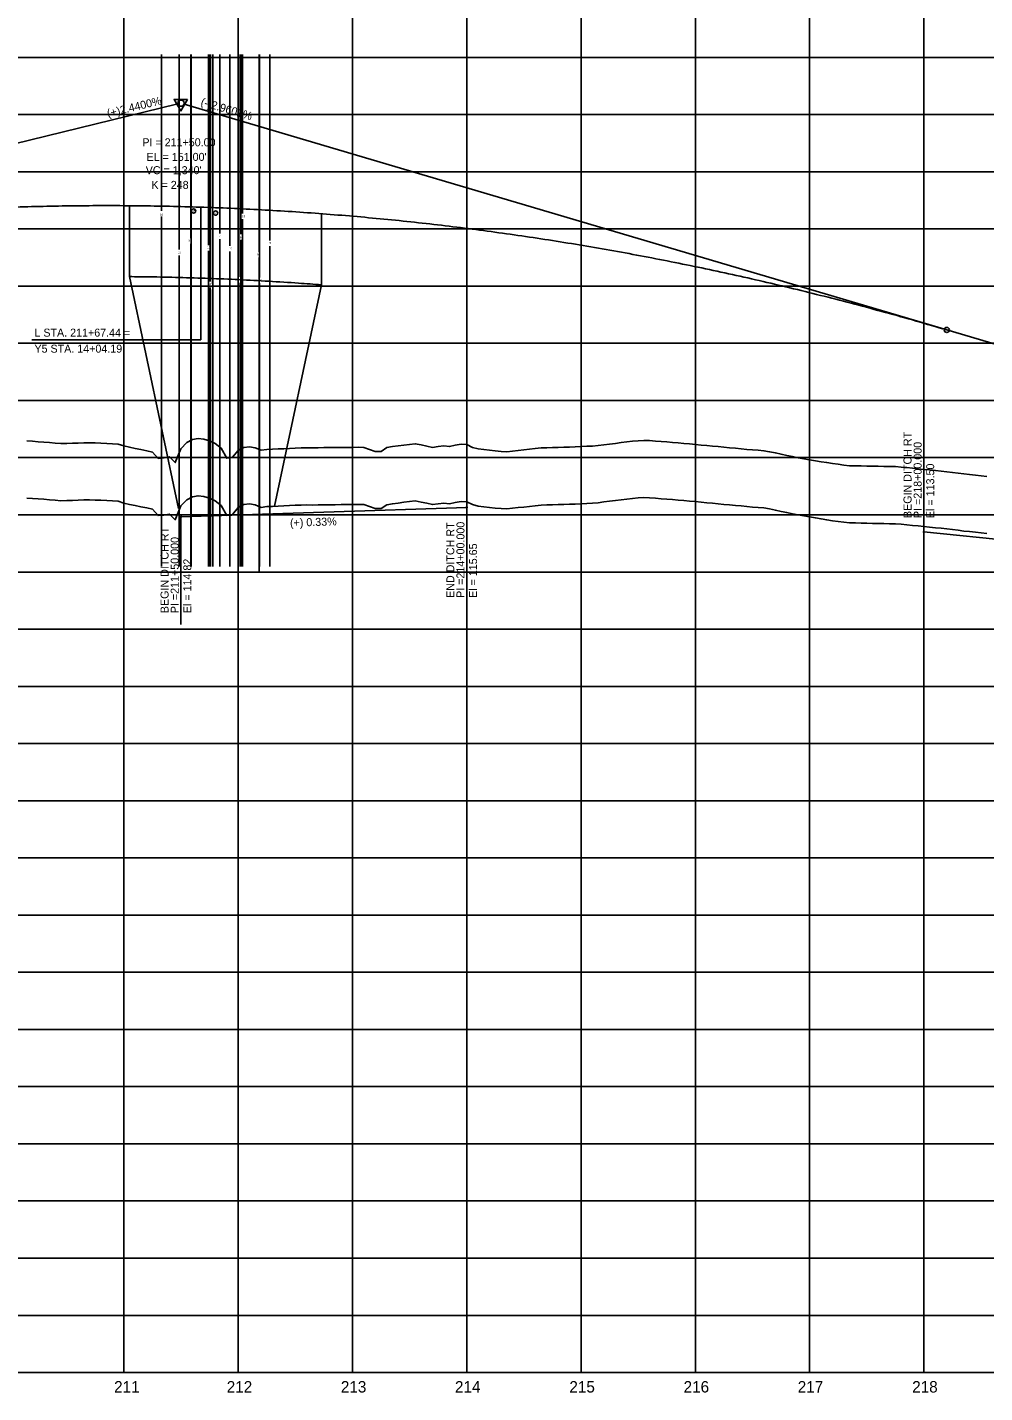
# Model space of a CAD drawing. Extents: x 2345490 to 2445302, y 465165 to 573888.
# Drawn here: x 2401337 to 2402175, y 564259 to 565453 of the extents above; entities that cross this region are included whole.
import ezdxf

# ---------------------------------------------------------------- set-up
doc = ezdxf.new("R2010")
doc.units = 0
for name, color, linetype in [('Old_Level_1', 7, 'Continuous'), ('Old_Level_2', 7, 'Continuous'), ('Old_Level_3', 7, 'Continuous'), ('Old_Level_57', 7, 'Continuous'), ('Old_Level_6', 7, 'Continuous'), ('Old_Level_62', 7, 'Continuous'), ('Old_Level_63', 7, 'Continuous')]:
    doc.layers.add(name, color=color, linetype=linetype)

msp = doc.modelspace()

# ---------------------------------------------------------------- linework, layer by layer
at = {"layer": 'Old_Level_1'}
for points in [[(2401336.5425, 565041.219), (2401341.5425, 565040.8905), (2401346.5425, 565040.512), (2401351.5425, 565040.09675), (2401356.5425, 565039.682), (2401361.5425, 565039.268), (2401366.5425, 565038.8545), (2401371.5425, 565038.982)], [(2401371.5425, 565038.982), (2401376.5425, 565039.15775), (2401381.5425, 565039.33375), (2401386.5425, 565039.5105), (2401391.5425, 565039.56925), (2401396.5425, 565039.418), (2401401.5425, 565039.24675), (2401406.5425, 565038.94875), (2401411.5425, 565038.652), (2401416.5425, 565038.3565), (2401421.5425, 565036.73225), (2401426.5425, 565035.699), (2401431.5425, 565034.66925), (2401436.5425, 565033.6435), (2401441.5425, 565032.6215), (2401446.5425, 565031.472), (2401451.5425, 565025.84975), (2401456.5425, 565026.37225), (2401461.5425, 565027.25675), (2401466.5425, 565022.21175), (2401471.5425, 565034.33175), (2401476.5425, 565039.72925), (2401481.5425, 565042.39775), (2401486.5425, 565043.2485), (2401491.5425, 565042.71025), (2401496.5425, 565041.198), (2401501.5425, 565038.84875), (2401506.5425, 565034.692), (2401511.5425, 565025.9635), (2401516.5425, 565026.869), (2401521.5425, 565032.8215), (2401526.5425, 565035.4635), (2401531.5425, 565036.07075), (2401536.5425, 565035.26475), (2401541.5425, 565032.9655), (2401546.5425, 565033.726), (2401551.5425, 565033.946), (2401556.5425, 565034.16775), (2401561.5425, 565034.39075), (2401566.5425, 565034.6155), (2401571.5425, 565034.842), (2401576.5425, 565035.06975), (2401581.5425, 565035.18775), (2401586.5425, 565035.1115), (2401591.5425, 565035.193), (2401596.5425, 565035.27525), (2401601.5425, 565035.35775), (2401606.5425, 565035.42275), (2401611.5425, 565035.4595), (2401616.5425, 565035.49725), (2401621.5425, 565035.53675), (2401626.5425, 565035.5775), (2401631.5425, 565035.5155), (2401636.5425, 565033.74), (2401641.5425, 565031.964), (2401646.5425, 565032.00875), (2401651.5425, 565035.38175), (2401656.5425, 565036.27475), (2401661.5425, 565036.8745), (2401666.5425, 565037.47475), (2401671.5425, 565038.07525), (2401676.5425, 565038.676), (2401681.5425, 565037.7145), (2401686.5425, 565036.6275), (2401691.5425, 565035.5405), (2401696.5425, 565036.1865), (2401701.5425, 565036.87), (2401706.5425, 565036.2335), (2401711.5425, 565037.34725), (2401716.5425, 565038.19), (2401721.5425, 565038.01175), (2401726.5425, 565035.504), (2401731.5425, 565034.129), (2401736.5425, 565033.57725), (2401741.5425, 565033.02725), (2401746.5425, 565032.47925), (2401751.5425, 565031.93325), (2401756.5425, 565031.67525), (2401761.5425, 565032.238), (2401766.5425, 565032.80225), (2401771.5425, 565033.36825), (2401776.5425, 565033.93575), (2401781.5425, 565034.50475), (2401786.5425, 565035.07525), (2401791.5425, 565035.27025), (2401796.5425, 565035.39175), (2401801.5425, 565035.51425), (2401806.5425, 565035.638), (2401811.5425, 565035.7625), (2401816.5425, 565035.9865), (2401821.5425, 565036.213), (2401826.5425, 565036.44075), (2401831.5425, 565036.66925), (2401836.5425, 565037.1695), (2401841.5425, 565037.7945), (2401846.5425, 565038.42075), (2401851.5425, 565039.0485), (2401856.5425, 565039.6775), (2401861.5425, 565040.30825), (2401866.5425, 565040.94025), (2401871.5425, 565041.3565)], [(2401871.5425, 565041.3565), (2401876.5425, 565041.65925), (2401881.5425, 565041.50575), (2401886.5425, 565041.07875), (2401891.5425, 565040.65225), (2401896.5425, 565040.22675), (2401901.5425, 565039.802), (2401906.5425, 565039.37825), (2401911.5425, 565038.95525), (2401916.5425, 565038.534), (2401921.5425, 565038.17625), (2401926.5425, 565037.58), (2401931.5425, 565037.10425), (2401936.5425, 565036.62875), (2401941.5425, 565036.154), (2401946.5425, 565035.6795), (2401951.5425, 565035.20575), (2401956.5425, 565034.73225), (2401961.5425, 565034.25925), (2401966.5425, 565033.78675), (2401971.5425, 565033.378), (2401976.5425, 565032.9915), (2401981.5425, 565032.6055), (2401986.5425, 565031.66725), (2401991.5425, 565030.61), (2401996.5425, 565029.5535), (2402001.5425, 565028.49775), (2402006.5425, 565027.44325), (2402011.5425, 565026.45875), (2402016.5425, 565025.5975), (2402021.5425, 565024.7365), (2402026.5425, 565023.876), (2402031.5425, 565023.01575), (2402036.5425, 565022.15575), (2402041.5425, 565021.36075), (2402046.5425, 565020.7135), (2402051.5425, 565020.06675), (2402056.5425, 565019.50775), (2402061.5425, 565019.4025), (2402066.5425, 565019.29775), (2402071.5425, 565019.19375), (2402076.5425, 565019.0905), (2402081.5425, 565018.988), (2402086.5425, 565018.886), (2402091.5425, 565018.78475), (2402096.5425, 565018.68425), (2402101.5425, 565018.322), (2402106.5425, 565017.81675), (2402111.5425, 565017.30675), (2402116.5425, 565016.79775), (2402121.5425, 565016.2895), (2402126.5425, 565015.78175), (2402131.5425, 565015.27475), (2402136.5425, 565014.7685), (2402141.5425, 565014.263), (2402146.5425, 565013.64675), (2402151.5425, 565013.01075), (2402156.5425, 565012.37925), (2402161.5425, 565011.824), (2402166.5425, 565011.2695), (2402171.5425, 565010.7155), (2402176.5425, 565010.162)]]:
    msp.add_lwpolyline(points, dxfattribs=at)
at = {"layer": 'Old_Level_2'}
for p, q in [((2400801.5425, 565223.054), (2401468.871, 565385.882)), ((2402141.5425, 565188.20425), (2401474.1795, 565385.75325)), ((2402141.5425, 565188.20425), (2402451.5425, 565096.43975))]:
    msp.add_line(p, q, dxfattribs=at)
msp.add_lwpolyline([(2401477.299, 565389.86625), (2401465.5565, 565389.85175), (2401471.44, 565379.7335)], close=True, dxfattribs=at)
for centre, radius in [((2401471.5425, 565386.534), 2.75), ((2402141.5425, 565188.20425), 2.25)]:
    msp.add_circle(centre, radius, dxfattribs=at)
msp.add_spline([(2400801.5425, 565223.054), (2400828.3425, 565229.44825), (2400855.1425, 565235.5535), (2400881.9425, 565241.369), (2400908.7425, 565246.895), (2400935.5425, 565252.13175), (2400962.3425, 565257.079), (2400989.1425, 565261.73675), (2401015.9425, 565266.10525), (2401042.7425, 565270.184), (2401069.5425, 565273.9735), (2401096.3425, 565277.4735), (2401123.1425, 565280.684), (2401149.9425, 565283.60525), (2401176.7425, 565286.23675), (2401203.5425, 565288.579), (2401230.3425, 565290.63175), (2401257.1425, 565292.395), (2401283.9425, 565293.869), (2401310.7425, 565295.05325), (2401337.5425, 565295.94825), (2401364.3425, 565296.55375), (2401391.1425, 565296.87), (2401417.9425, 565296.8965), (2401444.7425, 565296.63375), (2401471.5425, 565296.0815), (2401498.3425, 565295.23975), (2401525.1425, 565294.1085), (2401551.9425, 565292.688), (2401578.7425, 565290.978), (2401605.5425, 565288.9785), (2401632.3425, 565286.6895), (2401659.1425, 565284.111), (2401685.9425, 565281.24325), (2401712.7425, 565278.08575), (2401739.5425, 565274.639), (2401766.3425, 565270.903), (2401793.1425, 565266.87725), (2401819.9425, 565262.56225), (2401846.7425, 565257.95775), (2401873.5425, 565253.06375), (2401900.3425, 565247.88025), (2401927.1425, 565242.40725), (2401953.9425, 565236.645), (2401980.7425, 565230.59325), (2402007.5425, 565224.252), (2402034.3425, 565217.62125), (2402061.1425, 565210.70125), (2402087.9425, 565203.49175), (2402114.7425, 565195.99275), (2402141.5425, 565188.20425)], degree=3, dxfattribs=at)
at = {"layer": 'Old_Level_3'}
for p, q in [((2401488.9825, 565179.50175), (2401488.9825, 565295.56525)), ((2401341.176, 565179.50175), (2401488.9825, 565179.50175)), ((2402121.5425, 565098.35758), (2402121.5425, 565011.534)), ((2401471.5425, 565024.734), (2401721.5425, 565033.034)), ((2401721.5425, 565033.034), (2401721.5425, 564946.21042)), ((2401471.5425, 565024.734), (2401471.5425, 564930.52205)), ((2402121.5425, 565011.534), (2402371.5425, 564986.534))]:
    msp.add_line(p, q, dxfattribs=at)
for centre in [(2401721.5425, 565033.034), (2401471.5425, 565024.734), (2402121.5425, 565011.534)]:
    msp.add_circle(centre, 0.5, dxfattribs=at)
at = {"layer": 'Old_Level_57'}
for p, q in [((2401421.54225, 564276.534), (2401421.54225, 566615.2835)), ((2401521.54225, 564276.534), (2401521.54225, 566615.2835)), ((2401621.54225, 564276.534), (2401621.54225, 566615.2835)), ((2401721.54225, 564276.534), (2401721.54225, 566615.2835)), ((2401821.54225, 564276.534), (2401821.54225, 566615.2835)), ((2401921.54225, 564276.534), (2401921.54225, 566615.2835)), ((2402021.54225, 564276.534), (2402021.54225, 566615.2835)), ((2402121.54225, 564276.534), (2402121.54225, 566615.2835)), ((2381271.5425, 565426.534), (2410861.12275, 565426.534)), ((2381271.5425, 565376.534), (2410861.12275, 565376.534)), ((2381271.5425, 565326.534), (2410861.12275, 565326.534)), ((2381271.5425, 565276.534), (2410861.12275, 565276.534)), ((2381271.5425, 565226.534), (2410861.12275, 565226.534)), ((2381271.5425, 565176.534), (2410861.12275, 565176.534)), ((2381271.5425, 565126.534), (2410861.12275, 565126.534)), ((2381271.5425, 565076.534), (2410861.12275, 565076.534)), ((2381271.5425, 565026.534), (2410861.12275, 565026.534)), ((2381271.5425, 564976.534), (2410861.12275, 564976.534)), ((2381271.5425, 564926.534), (2410861.12275, 564926.534)), ((2381271.5425, 564876.534), (2410861.12275, 564876.534)), ((2381271.5425, 564826.534), (2410861.12275, 564826.534)), ((2381271.54275, 564776.534), (2410861.123, 564776.534)), ((2381271.5425, 564726.534), (2410861.12275, 564726.534)), ((2381271.54275, 564676.534), (2410861.123, 564676.534)), ((2381271.5425, 564626.534), (2410861.12275, 564626.534)), ((2381271.54275, 564576.534), (2410861.123, 564576.534)), ((2381271.5425, 564526.534), (2410861.12275, 564526.534)), ((2381271.54275, 564476.534), (2410861.123, 564476.534)), ((2381271.5425, 564426.534), (2410861.12275, 564426.534)), ((2381271.54275, 564376.534), (2410861.123, 564376.534)), ((2381271.5425, 564326.534), (2410861.12275, 564326.534)), ((2381271.54275, 564276.534), (2410861.123, 564276.534))]:
    msp.add_line(p, q, dxfattribs=at)
at = {"layer": 'Old_Level_6'}
for p, q in [((2401426.4825, 565234.84025), (2401426.4825, 565296.843)), ((2401594.3725, 565227.6645), (2401594.3725, 565289.847)), ((2401469.4655, 565032.08975), (2401426.4825, 565234.84025)), ((2401594.3725, 565227.6645), (2401553.32075, 565034.024))]:
    msp.add_line(p, q, dxfattribs=at)
msp.add_spline([(2401426.4825, 565234.84125), (2401443.8, 565234.64), (2401469.9305, 565234.1015), (2401496.062, 565233.28075), (2401522.19425, 565232.17775), (2401548.3275, 565230.7925), (2401574.462, 565229.125), (2401594.3725, 565227.665)], degree=3, dxfattribs=at)
at = {"layer": 'Old_Level_63'}
for p, q in [((2401454.4425, 565292.434), (2401454.4425, 565429.1655)), ((2401470.0525, 565258.434), (2401470.0525, 565429.1655)), ((2401480.1925, 565268.434), (2401480.1925, 565429.1655)), ((2401480.5125, 565296.334), (2401480.5125, 565429.1655)), ((2401495.6925, 565262.434), (2401495.6925, 565429.1655)), ((2401497.0925, 565230.434), (2401497.0925, 565429.1655)), ((2401499.0025, 565228.534), (2401499.0025, 565429.1655)), ((2401499.4725, 565295.634), (2401499.4725, 565429.1655)), ((2401505.5625, 565272.534), (2401505.5625, 565429.1655)), ((2401514.3425, 565261.834), (2401514.3425, 565429.1655)), ((2401522.0025, 565234.534), (2401522.0025, 565429.1655)), ((2401524.0125, 565271.934), (2401524.0125, 565429.1655)), ((2401525.4125, 565290.034), (2401525.4125, 565429.1655)), ((2401539.8625, 565256.434), (2401539.8625, 565429.1655)), ((2401540.1225, 565234.034), (2401540.1225, 565429.1655)), ((2401549.2425, 565266.534), (2401549.2425, 565429.1655)), ((2401480.5125, 565291.334), (2401480.5125, 564981.40175)), ((2401454.4425, 565287.434), (2401454.4425, 564981.40175)), ((2401499.4725, 565290.634), (2401499.4725, 564981.40175)), ((2401525.4125, 565285.034), (2401525.4125, 564981.40175)), ((2401505.5625, 565267.534), (2401505.5625, 564981.40175)), ((2401480.1925, 565263.434), (2401480.1925, 564981.40175)), ((2401495.6925, 565257.434), (2401495.6925, 564981.40175)), ((2401514.3425, 565256.834), (2401514.3425, 564981.40175)), ((2401524.0125, 565266.934), (2401524.0125, 564981.40175)), ((2401549.2425, 565261.534), (2401549.2425, 564981.40175)), ((2401470.0525, 565253.434), (2401470.0525, 564981.40175)), ((2401539.8625, 565251.434), (2401539.8625, 564977.09475)), ((2401497.0925, 565225.434), (2401497.0925, 564981.40175)), ((2401499.0025, 565223.534), (2401499.0025, 564981.40175)), ((2401522.0025, 565229.534), (2401522.0025, 564981.40175)), ((2401540.1225, 565229.034), (2401540.1225, 564981.40175)), ((2381321.5425, 564276.534), (2406689.937, 564276.534))]:
    msp.add_line(p, q, dxfattribs=at)
for points in [[(2401336.5425, 565091.218), (2401341.5425, 565090.8895), (2401346.5425, 565090.51125), (2401351.5425, 565090.096), (2401356.5425, 565089.68125), (2401361.5425, 565089.26725), (2401366.5425, 565088.85375), (2401371.5425, 565088.98125)], [(2401371.5425, 565088.98125), (2401376.5425, 565089.15675), (2401381.5425, 565089.333), (2401386.5425, 565089.50975), (2401391.5425, 565089.56725), (2401396.5425, 565089.416), (2401401.5425, 565089.245), (2401406.5425, 565088.94675), (2401411.5425, 565088.65), (2401416.5425, 565088.3545), (2401421.5425, 565086.7275), (2401426.5425, 565085.694), (2401431.5425, 565084.66425), (2401436.5425, 565083.6385), (2401441.5425, 565082.61625), (2401446.5425, 565081.47825), (2401451.5425, 565075.849), (2401456.5425, 565076.3725), (2401461.5425, 565077.257), (2401466.5425, 565072.22025), (2401471.5425, 565084.3075), (2401476.5425, 565089.72075), (2401481.5425, 565092.39525), (2401486.5425, 565093.24625), (2401491.5425, 565092.71075), (2401496.5425, 565091.19825), (2401501.5425, 565088.85225), (2401506.5425, 565084.695), (2401511.5425, 565075.972), (2401516.5425, 565076.85775), (2401521.5425, 565082.81875), (2401526.5425, 565085.46075), (2401531.5425, 565086.066), (2401536.5425, 565085.26), (2401541.5425, 565082.96375), (2401546.5425, 565083.723), (2401551.5425, 565083.94325), (2401556.5425, 565084.16475), (2401561.5425, 565084.388), (2401566.5425, 565084.61275), (2401571.5425, 565084.839), (2401576.5425, 565085.06675), (2401581.5425, 565085.18575), (2401586.5425, 565085.1105), (2401591.5425, 565085.192), (2401596.5425, 565085.274), (2401601.5425, 565085.3565), (2401606.5425, 565085.42), (2401611.5425, 565085.4565), (2401616.5425, 565085.4945), (2401621.5425, 565085.534), (2401626.5425, 565085.57475), (2401631.5425, 565085.5175), (2401636.5425, 565083.742), (2401641.5425, 565081.96575), (2401646.5425, 565082.003), (2401651.5425, 565085.37875), (2401656.5425, 565086.27375), (2401661.5425, 565086.8735), (2401666.5425, 565087.47375), (2401671.5425, 565088.07425), (2401676.5425, 565088.67475), (2401681.5425, 565087.7145), (2401686.5425, 565086.6275), (2401691.5425, 565085.5405), (2401696.5425, 565086.17825), (2401701.5425, 565086.8605), (2401706.5425, 565086.23175), (2401711.5425, 565087.3455), (2401716.5425, 565088.18725), (2401721.5425, 565088.0195), (2401726.5425, 565085.50525), (2401731.5425, 565084.125), (2401736.5425, 565083.573), (2401741.5425, 565083.02325), (2401746.5425, 565082.475), (2401751.5425, 565081.929), (2401756.5425, 565081.67125), (2401761.5425, 565082.234), (2401766.5425, 565082.7985), (2401771.5425, 565083.36425), (2401776.5425, 565083.93175), (2401781.5425, 565084.50075), (2401786.5425, 565085.07125), (2401791.5425, 565085.2675), (2401796.5425, 565085.389), (2401801.5425, 565085.51175), (2401806.5425, 565085.63525), (2401811.5425, 565085.75975), (2401816.5425, 565085.98375), (2401821.5425, 565086.21025), (2401826.5425, 565086.438), (2401831.5425, 565086.66675), (2401836.5425, 565087.1655), (2401841.5425, 565087.7905), (2401846.5425, 565088.41675), (2401851.5425, 565089.0445), (2401856.5425, 565089.6735), (2401861.5425, 565090.30425), (2401866.5425, 565090.936), (2401871.5425, 565091.35225)], [(2401871.5425, 565091.35225), (2401876.5425, 565091.65525), (2401881.5425, 565091.50375), (2401886.5425, 565091.07675), (2401891.5425, 565090.6505), (2401896.5425, 565090.22475), (2401901.5425, 565089.80025), (2401906.5425, 565089.37625), (2401911.5425, 565088.95325), (2401916.5425, 565088.531), (2401921.5425, 565088.17325), (2401926.5425, 565087.57875), (2401931.5425, 565087.103), (2401936.5425, 565086.62775), (2401941.5425, 565086.15275), (2401946.5425, 565085.6785), (2401951.5425, 565085.2045), (2401956.5425, 565084.731), (2401961.5425, 565084.25825), (2401966.5425, 565083.78575), (2401971.5425, 565083.37675), (2401976.5425, 565082.99), (2401981.5425, 565082.604), (2401986.5425, 565081.6655), (2401991.5425, 565080.608), (2401996.5425, 565079.5515), (2402001.5425, 565078.496), (2402006.5425, 565077.44125), (2402011.5425, 565076.45825), (2402016.5425, 565075.597), (2402021.5425, 565074.73625), (2402026.5425, 565073.8755), (2402031.5425, 565073.01525), (2402036.5425, 565072.15525), (2402041.5425, 565071.3605), (2402046.5425, 565070.7135), (2402051.5425, 565070.0665), (2402056.5425, 565069.50575), (2402061.5425, 565069.4005), (2402066.5425, 565069.29575), (2402071.5425, 565069.19175), (2402076.5425, 565069.0885), (2402081.5425, 565068.98575), (2402086.5425, 565068.88375), (2402091.5425, 565068.7825), (2402096.5425, 565068.682), (2402101.5425, 565068.31975), (2402106.5425, 565067.81475), (2402111.5425, 565067.305), (2402116.5425, 565066.796), (2402121.5425, 565066.2875), (2402126.5425, 565065.77975), (2402131.5425, 565065.273), (2402136.5425, 565064.76675), (2402141.5425, 565064.26125), (2402146.5425, 565063.64525), (2402151.5425, 565063.0095), (2402156.5425, 565062.37775), (2402161.5425, 565061.8225), (2402166.5425, 565061.268), (2402171.5425, 565060.714), (2402176.5425, 565060.16075)]]:
    msp.add_lwpolyline(points, dxfattribs=at)
for centre in [(2401482.53351, 565292.21498), (2401501.80488, 565290.38951)]:
    msp.add_circle(centre, 1.8696, dxfattribs=at)

# ---------------------------------------------------------------- texts
at = {"layer": 'Old_Level_2'}
for s, rotation, p in [('(+)2.4400%', 13.71223611, (2401407.71925, 565374.04875)), ('(-)2.9601%', 343.51048333, (2401488.29175, 565384.7045))]:
    msp.add_text(s, height=7.000001, rotation=rotation, dxfattribs=at).set_placement(p)
for s, height, p in [('PI = 211+50.00', 7.0000005, (2401437.75075, 565348.796)), ("EL = 151.00'", 7.0000005, (2401441.37525, 565336.0475)), ("VC = 1,340'", 7.0000005, (2401440.65875, 565324.4055)), ('K = 248', 7.000001, (2401445.69425, 565311.54125))]:
    msp.add_text(s, height=height, dxfattribs=at).set_placement(p)
at = {"layer": 'Old_Level_3'}
for s, p in [('L STA. 211+67.44 = ', (2401343.33, 565182.3455)), ('Y5 STA. 14+04.19', (2401343.33, 565168.34525))]:
    msp.add_text(s, height=7.0000005, dxfattribs=at).set_placement(p)
for s, height, rotation, p in [('BEGIN DITCH RT', 7.0000005, 90, (2402110.6686, 565023.71663)), ('PI =218+00.000', 7.0000005, 90, (2402119.5425, 565023.71663)), ('El = 113.50', 7.0000005, 90, (2402130.5425, 565023.71663)), ('(+) 0.33%', 7, 1.90152222, (2401567.02353, 565016.04367)), ('END DITCH RT', 7.0000005, 90, (2401710.6686, 564953.88786)), ('PI =214+00.000', 7.0000005, 90, (2401719.5425, 564953.88786)), ('BEGIN DITCH RT', 7.0000005, 90, (2401460.6686, 564940.54516)), ('PI =211+50.000', 7.0000005, 90, (2401469.5425, 564940.54516)), ('El = 115.65', 7.0000005, 90, (2401730.5425, 564953.88786)), ('El = 114.82', 7.0000005, 90, (2401480.5425, 564940.54516))]:
    msp.add_text(s, height=height, rotation=rotation, dxfattribs=at).set_placement(p)
at = {"layer": 'Old_Level_62'}
for s, p in [('211', (2401413.01075, 564259.034)), ('212', (2401511.55925, 564259.034)), ('213', (2401611.394, 564259.034)), ('214', (2401711.2365, 564259.034)), ('215', (2401811.329, 564259.034)), ('216', (2401911.27, 564259.034)), ('217', (2402011.1275, 564259.034)), ('218', (2402111.25325, 564259.034))]:
    msp.add_text(s, height=10.000001, dxfattribs=at).set_placement(p)
at = {"layer": 'Old_Level_63'}
for s, height, p in [('15', 1.750001, (2401481.40525, 565291.269)), ('14', 1.750001, (2401500.88375, 565289.68125)), ('16', 1.750001, (2401453.22325, 565288.22925)), ('13', 1.750001, (2401524.94625, 565286.8245)), ('7', 1.75, (2401504.81575, 565269.24525)), ('6', 1.75, (2401523.05025, 565268.3045)), ('12', 1.750001, (2401468.7955, 565255.28575)), ('8', 1.75, (2401477.96575, 565265.2895)), ('11', 1.750001, (2401494.4215, 565259.3465)), ('10', 1.750001, (2401513.3905, 565258.85525)), ('5', 1.75, (2401549.05675, 565263.3975)), ('9', 1.75, (2401537.949, 565253.0415)), ('3', 1.75, (2401521.03375, 565231.40025)), ('2', 1.75, (2401540.56725, 565230.7615)), ('4', 1.75, (2401496.34875, 565227.42125)), ('1', 1.75, (2401498.3175, 565225.53675))]:
    msp.add_text(s, height=height, dxfattribs=at).set_placement(p)

doc.saveas('drawing.dxf')
